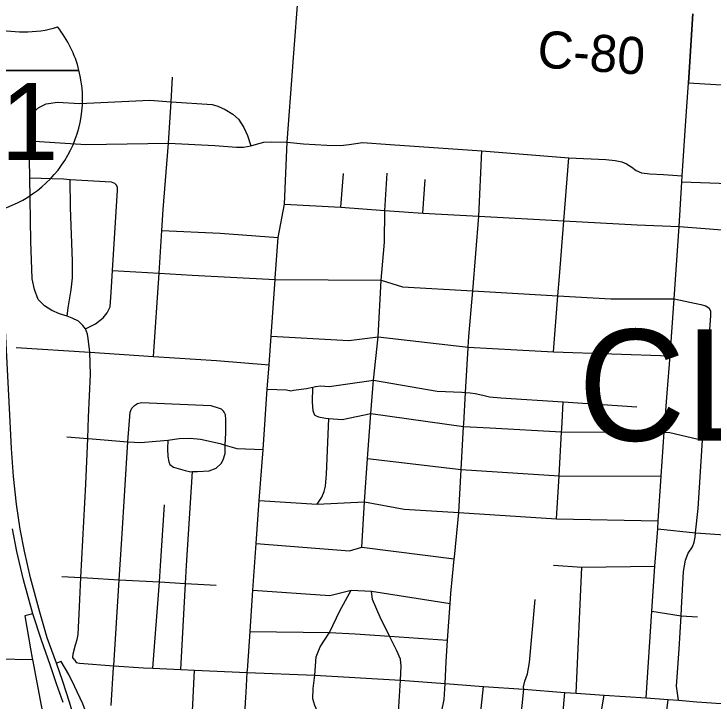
# Model space of a CAD drawing. Extents: x 0 to 34, y 0 to 22.
# Drawn here: x 6.488 to 7.561, y 16.128 to 17.181 of the extents above; entities that cross this region are included whole.
import ezdxf

# ---------------------------------------------------------------- set-up
doc = ezdxf.new("R2010")
doc.units = 0
for name, color, linetype in [('GM_X_City_Street', 7, 'Continuous'), ('GM_X_County_Road', 7, 'Continuous'), ('GM_X_County_Road_Text', 7, 'Continuous'), ('GM_X_Interchange_Ramps', 7, 'Continuous'), ('GM_X_Interstate_Route', 7, 'Continuous'), ('GM_X_Interstate_Shield', 7, 'Continuous'), ('GM_X_Township_Text', 7, 'Continuous')]:
    doc.layers.add(name, color=color, linetype=linetype)

msp = doc.modelspace()

# ---------------------------------------------------------------- linework, layer by layer
at = {"layer": 'GM_X_City_Street'}
for p, q in [((7.5231, 17.0753), (7.5298, 17.1813)), ((7.5185, 17.0096), (7.5231, 17.0753)), ((6.99, 16.8851), (6.9938, 16.9368)), ((7.1155, 16.876), (7.119, 16.9272)), ((6.5694, 16.5328), (6.6015, 16.5303)), ((7.4757, 16.3921), (7.5338, 16.3856)), ((7.3509, 16.14), (7.3593, 16.3332)), ((6.4444, 16.1929), (6.5167, 16.1915)), ((6.8444, 16.141), (6.8462, 16.1716))]:
    msp.add_line(p, q, dxfattribs=at)
for points in [[(6.9167, 17.1078), (6.9254, 17.2217), (6.938, 17.4228), (6.9444, 17.5239), (6.9541, 17.675), (6.9597, 17.764), (6.9633, 17.8201), (6.9689, 17.9079), (6.973, 17.9724), (6.9772, 18.0377), (6.9864, 18.1488)], [(6.8469, 16.1818), (6.8505, 16.2343), (6.8548, 16.298), (6.8597, 16.3693), (6.8646, 16.4353), (6.8705, 16.5136), (6.877, 16.606), (6.8797, 16.6435), (6.8828, 16.6872), (6.8889, 16.7741), (6.8891, 16.7759), (6.8935, 16.8385), (6.9033, 16.8894), (6.9074, 16.9846), (6.9161, 17.1002), (6.9167, 17.1078)], [(6.7027, 16.6561), (6.7111, 16.7836), (6.7154, 16.8492), (6.7175, 16.8815), (6.7257, 16.983), (6.7293, 17.0465), (6.7314, 17.0841)], [(6.525, 17.0367), (6.5295, 17.0394), (6.5379, 17.0435), (6.555, 17.046), (6.5895, 17.0441), (6.6969, 17.0489), (6.7293, 17.0465), (6.7922, 17.0421), (6.801, 17.0397), (6.8123, 17.0349), (6.824, 17.0274), (6.8329, 17.0196), (6.8409, 17.0072), (6.8467, 16.9946), (6.8519, 16.9789)], [(6.5812, 16.1911), (6.5789, 16.1945), (6.579, 16.2002), (6.5829, 16.2142), (6.5853, 16.2222), (6.5868, 16.2298), (6.5888, 16.2723), (6.5911, 16.3172), (6.5985, 16.4605), (6.6015, 16.5303), (6.6028, 16.5629), (6.6057, 16.6286), (6.6047, 16.6625), (6.6025, 16.6837), (6.601, 16.6905), (6.598, 16.6985), (6.5939, 16.7035), (6.5872, 16.71), (6.5777, 16.715), (6.57, 16.7176), (6.5584, 16.7213), (6.5463, 16.7264), (6.5354, 16.7337), (6.5256, 16.7436), (6.5197, 16.7585), (6.5165, 16.7752), (6.5143, 16.8326), (6.5128, 16.9298), (6.5119, 16.9867), (6.5117, 17.0004), (6.5126, 17.0152), (6.5157, 17.0243), (6.5207, 17.0319), (6.525, 17.0367)], [(7.4583, 16.1326), (7.4667, 16.2655), (7.4715, 16.3347), (7.4757, 16.3921), (7.4766, 16.4039), (7.4813, 16.4726), (7.4858, 16.5402), (7.4905, 16.6), (7.495, 16.6573), (7.5009, 16.7446), (7.5088, 16.8554), (7.5126, 16.9236), (7.5132, 16.9329), (7.5185, 17.0096)], [(6.5119, 16.9867), (6.5988, 16.981), (6.7257, 16.983), (6.7963, 16.9797), (6.8298, 16.9769), (6.8407, 16.9768), (6.8519, 16.9789), (6.8604, 16.9814), (6.8715, 16.9844), (6.8832, 16.9853), (6.9074, 16.9846), (6.9327, 16.9821), (6.9684, 16.9802), (6.9894, 16.9795), (7.0023, 16.9808), (7.0127, 16.9827), (7.0228, 16.984), (7.0656, 16.9812), (7.2059, 16.9713), (7.3394, 16.9608), (7.3963, 16.9578), (7.4105, 16.9564), (7.4209, 16.9543), (7.4279, 16.9515), (7.4361, 16.9462), (7.4426, 16.941), (7.451, 16.9375), (7.4636, 16.9359), (7.4845, 16.9348), (7.5132, 16.9329)], [(7.1403, 16.1023), (7.1443, 16.1105), (7.148, 16.1301), (7.1499, 16.1549), (7.1514, 16.1882), (7.1536, 16.2211), (7.1573, 16.2776), (7.1587, 16.2925), (7.1637, 16.346), (7.164, 16.3483), (7.1705, 16.4167), (7.1742, 16.4828), (7.1781, 16.5489), (7.1783, 16.5528), (7.1812, 16.6009), (7.1852, 16.6693), (7.1853, 16.6704), (7.1862, 16.6867), (7.192, 16.7566), (7.2015, 16.8713), (7.2059, 16.9713)], [(7.3157, 16.6632), (7.3227, 16.749), (7.3252, 16.7788), (7.3318, 16.8642), (7.3394, 16.9608)], [(6.5128, 16.9298), (6.5645, 16.9282), (6.5744, 16.9276), (6.6373, 16.924), (6.6426, 16.9217), (6.6452, 16.9194)], [(7.0219, 16.3637), (7.0263, 16.4333), (7.0306, 16.4997), (7.0356, 16.5687), (7.04, 16.6197), (7.0468, 16.6861), (7.0518, 16.7731), (7.0567, 16.8315), (7.0574, 16.8798), (7.0609, 16.9373)], [(6.57, 16.7176), (6.5718, 16.7307), (6.5762, 16.7583), (6.5783, 16.7765), (6.5781, 16.802), (6.5751, 16.8844), (6.5744, 16.9276)], [(6.598, 16.6985), (6.6133, 16.7063), (6.6255, 16.7153), (6.6313, 16.7232), (6.6359, 16.7323), (6.6376, 16.7543), (6.6397, 16.7881), (6.6474, 16.911), (6.6471, 16.9156), (6.6452, 16.9194)], [(7.5126, 16.9236), (7.5701, 16.9219), (7.6237, 16.9188), (7.6813, 16.915), (7.7077, 16.9123)], [(6.9033, 16.8894), (6.99, 16.8851), (7.0574, 16.8798), (7.1155, 16.876), (7.2015, 16.8713), (7.3318, 16.8642), (7.444, 16.858), (7.5088, 16.8554), (7.7004, 16.8406)], [(6.7154, 16.8492), (6.8046, 16.845), (6.8935, 16.8385)], [(6.6397, 16.7881), (6.7111, 16.7836), (6.7619, 16.7805), (6.8889, 16.7741), (7.0518, 16.7731), (7.0845, 16.7629), (7.192, 16.7566), (7.3227, 16.749), (7.4041, 16.7442), (7.5009, 16.7446), (7.5421, 16.7357), (7.5497, 16.7337), (7.5549, 16.7302)], [(7.5078, 16.129), (7.5044, 16.1506), (7.5087, 16.2075), (7.5117, 16.2584), (7.5123, 16.2701), (7.5155, 16.3263), (7.5183, 16.3437), (7.5226, 16.3547), (7.5292, 16.3645), (7.5315, 16.3713), (7.5331, 16.3789), (7.5338, 16.3856), (7.5377, 16.4229), (7.5445, 16.5279), (7.5523, 16.6471), (7.5571, 16.7184), (7.5572, 16.7253), (7.5549, 16.7302)], [(6.8828, 16.6872), (7.0018, 16.6805), (7.0468, 16.6861), (7.1853, 16.6704), (7.2596, 16.6663), (7.3157, 16.6632), (7.495, 16.6573)], [(6.492, 16.6696), (6.6047, 16.6625), (6.7027, 16.6561), (6.799, 16.6499), (6.8797, 16.6435)], [(6.877, 16.606), (6.9063, 16.6048), (6.9131, 16.6036), (6.9173, 16.6043), (6.937, 16.6071), (6.9467, 16.6091), (6.9511, 16.61), (6.9587, 16.6111), (6.972, 16.6102), (7.04, 16.6197), (7.1377, 16.6029), (7.1752, 16.6011), (7.1812, 16.6009), (7.1881, 16.6005), (7.1957, 16.5993), (7.2074, 16.5969), (7.2176, 16.5942), (7.235, 16.5929), (7.3309, 16.5865), (7.4439, 16.5791)], [(6.9511, 16.5656), (6.9499, 16.5656), (6.9473, 16.5725), (6.9463, 16.5862), (6.9467, 16.6091)], [(7.3206, 16.4074), (7.3244, 16.4731), (7.3283, 16.5404), (7.3285, 16.5444), (7.3309, 16.5865)], [(6.6376, 16.1212), (6.6413, 16.1794), (6.6414, 16.182), (6.6498, 16.3139), (6.6537, 16.3758), (6.6632, 16.5253), (6.6668, 16.5706), (6.6692, 16.5766), (6.6731, 16.5807)], [(6.6731, 16.5807), (6.6777, 16.584), (6.6838, 16.5854), (6.7902, 16.5809), (6.8015, 16.5773), (6.8064, 16.5756), (6.8097, 16.5721)], [(6.8124, 16.5201), (6.8132, 16.539), (6.8133, 16.5595), (6.8127, 16.5668), (6.8108, 16.5706), (6.8097, 16.5721)], [(6.9511, 16.5656), (6.9556, 16.5633), (6.9662, 16.5613), (6.9716, 16.5609), (6.992, 16.5592), (7.0356, 16.5687), (7.1781, 16.5489), (7.2183, 16.5467), (7.3283, 16.5404), (7.4858, 16.5402), (7.4945, 16.5396), (7.5445, 16.5279)], [(6.9537, 16.4299), (6.9605, 16.4406), (6.964, 16.4493), (6.9664, 16.4573), (6.9677, 16.4755), (6.9716, 16.5609)], [(6.6015, 16.5303), (6.6084, 16.5297), (6.6632, 16.5253), (6.6825, 16.5243), (6.7064, 16.5261), (6.7243, 16.528), (6.7418, 16.5303), (6.7588, 16.5307), (6.7747, 16.5292), (6.8045, 16.5225), (6.8124, 16.5201), (6.8302, 16.5152), (6.8705, 16.5136)], [(6.7243, 16.528), (6.724, 16.5144), (6.7242, 16.5026), (6.7259, 16.4946), (6.7277, 16.4904), (6.7329, 16.4865), (6.751, 16.4811), (6.7597, 16.4794), (6.7621, 16.4795), (6.7699, 16.4796), (6.7878, 16.4808), (6.7988, 16.4851), (6.8062, 16.4918), (6.8093, 16.4978), (6.8122, 16.5072), (6.8124, 16.5201)], [(7.0306, 16.4997), (7.1742, 16.4828), (7.3244, 16.4731), (7.4813, 16.4726)], [(6.7446, 16.1762), (6.7517, 16.3082), (6.7532, 16.3356), (6.7621, 16.4795)], [(6.7013, 16.1781), (6.7115, 16.3104), (6.7134, 16.3352), (6.7192, 16.4286)], [(6.8646, 16.4353), (6.9537, 16.4299), (7.0263, 16.4333), (7.0867, 16.4219), (7.1705, 16.4167), (7.3206, 16.4074), (7.4766, 16.4039)], [(7.5338, 16.3856), (7.5859, 16.3823), (7.5957, 16.3817), (7.6887, 16.3758), (7.7429, 16.3724), (7.7927, 16.3693), (7.794, 16.3692), (7.7947, 16.3691), (7.8021, 16.3686)], [(6.8597, 16.3693), (7.003, 16.3582), (7.0219, 16.3637), (7.1637, 16.346)], [(7.3157, 16.3362), (7.3593, 16.3332), (7.4715, 16.3347)], [(6.5619, 16.3188), (6.5911, 16.3172), (6.6014, 16.3166), (6.6498, 16.3139), (6.7115, 16.3104), (6.7517, 16.3082), (6.7988, 16.3055)], [(6.8548, 16.298), (6.9728, 16.2894), (7.0056, 16.2977), (7.0367, 16.2962), (7.1573, 16.2776)], [(6.963, 16.1046), (6.9541, 16.1116), (6.9497, 16.1208), (6.9467, 16.1312), (6.9475, 16.1471), (6.9499, 16.1673), (6.9519, 16.1956), (6.9582, 16.2108), (6.9726, 16.233), (6.9882, 16.2659), (7.0056, 16.2977)], [(7.0028, 14.93), (7.0083, 15.046), (7.0115, 15.0984), (7.013, 15.1274), (7.018, 15.2086), (7.0267, 15.3678), (7.0381, 15.5628), (7.0466, 15.7049), (7.0589, 15.85), (7.0692, 15.9713), (7.0729, 16.0317), (7.077, 16.0946), (7.0811, 16.1597), (7.0822, 16.1815), (7.0811, 16.1919), (7.0759, 16.2048), (7.0644, 16.2274), (7.05, 16.2563), (7.0381, 16.2833), (7.0367, 16.2962)], [(7.186, 15.039), (7.1895, 15.1078), (7.1929, 15.1743), (7.1982, 15.2632), (7.2036, 15.352), (7.2068, 15.4104), (7.2196, 15.5508), (7.2262, 15.6871), (7.2263, 15.6891), (7.2401, 15.8332), (7.2424, 15.8578), (7.2566, 16.0106), (7.2706, 16.1462), (7.2698, 16.1495), (7.2721, 16.1585), (7.2763, 16.1698), (7.2792, 16.1871), (7.2876, 16.2833)], [(7.4667, 16.2655), (7.5117, 16.2584), (7.5368, 16.2567)], [(6.8505, 16.2343), (6.9726, 16.233), (7.0119, 16.2308), (7.0644, 16.2274), (7.1536, 16.2211)], [(6.5812, 16.1911), (6.5838, 16.1869), (6.5891, 16.1857), (6.6414, 16.182), (6.6873, 16.1787), (6.7013, 16.1781), (6.7446, 16.1762), (6.7655, 16.1752), (6.8462, 16.1716)], [(6.8462, 16.1716), (6.8463, 16.1735), (6.8464, 16.1745), (6.8469, 16.1818)], [(6.7312, 15.579), (6.7356, 15.6398), (6.7376, 15.6683), (6.7384, 15.6782), (6.7405, 15.7181), (6.7438, 15.7776), (6.7449, 15.7973), (6.7457, 15.8121), (6.7465, 15.8265), (6.7493, 15.8768), (6.7495, 15.8787), (6.7523, 15.9294), (6.7543, 15.9643), (6.7555, 15.987), (6.7587, 16.0471), (6.7621, 16.1122), (6.7655, 16.1752)], [(7.1183, 14.9866), (7.1158, 14.9898), (7.1158, 15), (7.1164, 15.0163), (7.1189, 15.0303), (7.1214, 15.0378), (7.1223, 15.0425), (7.1239, 15.0517), (7.1249, 15.0665), (7.1273, 15.1115), (7.1333, 15.223), (7.1358, 15.2675), (7.1442, 15.4144), (7.1442, 15.4159), (7.1577, 15.555), (7.1638, 15.6726), (7.1656, 15.6911), (7.1722, 15.76), (7.1778, 15.8163), (7.1795, 15.837), (7.1995, 16.0231), (7.196, 16.0294), (7.2087, 16.1503)], [(6.8387, 16.0479), (6.8439, 16.1339), (6.8444, 16.141)], [(7.2801, 14.9329), (7.279, 14.9757), (7.279, 15.036), (7.2786, 15.1026), (7.2778, 15.2648), (7.2782, 15.3396), (7.2767, 15.4062), (7.2778, 15.478), (7.2823, 15.5476), (7.2929, 15.6588), (7.2948, 15.6907), (7.2975, 15.7129), (7.302, 15.7683), (7.3079, 15.8357), (7.3225, 16.0168), (7.3333, 16.1408)], [(7.419, 15.8228), (7.4178, 15.8288), (7.4171, 15.8414), (7.4175, 15.8706), (7.4204, 15.8963), (7.4204, 15.9141), (7.4175, 15.9268), (7.4114, 15.9361), (7.3937, 15.9505), (7.3876, 15.9557), (7.3838, 15.9589), (7.3795, 15.9644), (7.3768, 15.9732), (7.3757, 15.9835), (7.3774, 16.0024), (7.3777, 16.0058), (7.3823, 16.0706), (7.3936, 16.1368)], [(7.4723, 15.5328), (7.4764, 15.593), (7.4677, 15.5947), (7.4606, 15.5973), (7.4562, 15.6016), (7.4534, 15.6096), (7.4523, 15.6233), (7.4535, 15.642), (7.4557, 15.6778), (7.4567, 15.6944), (7.46, 15.7475), (7.4625, 15.7886), (7.4645, 15.8202), (7.4754, 15.9962), (7.4919, 16.13)]]:
    msp.add_lwpolyline(points, dxfattribs=at)
at = {"layer": 'GM_X_County_Road'}
msp.add_line((7.5298, 17.1813), (7.5231, 17.0753), dxfattribs=at)
for points in [[(7.5231, 17.0753), (7.6154, 17.0697), (7.9476, 17.0504), (8.2133, 17.0321), (8.2203, 17.0317), (8.2262, 17.0314)], [(6.8462, 16.1716), (6.9499, 16.1673), (7.0811, 16.1597), (7.1499, 16.1549), (7.2087, 16.1503), (7.2706, 16.1462), (7.3333, 16.1408), (7.3509, 16.14), (7.3936, 16.1368), (7.4583, 16.1326), (7.4919, 16.13), (7.5078, 16.129), (7.536, 16.1269), (7.6025, 16.1222), (7.7152, 16.1151), (7.7857, 16.1102), (7.8462, 16.1057), (7.9125, 16.101), (7.9759, 16.0969), (8.0366, 16.0924), (8.2099, 16.0817), (8.2195, 16.0811)]]:
    msp.add_lwpolyline(points, dxfattribs=at)
at = {"layer": 'GM_X_Interchange_Ramps'}
for points in [[(6.5174, 16.2615), (6.5049, 16.2587), (6.5136, 16.2078), (6.5163, 16.1937)], [(6.5163, 16.1937), (6.5167, 16.1915), (6.5302, 16.1211), (6.5386, 16.0808), (6.5403, 16.0714)], [(6.6127, 16.0642), (6.6111, 16.0729), (6.6034, 16.0983), (6.5939, 16.1237), (6.5814, 16.1505), (6.5725, 16.1684), (6.561, 16.1883), (6.5538, 16.1858)]]:
    msp.add_lwpolyline(points, dxfattribs=at)
at = {"layer": 'GM_X_Interstate_Route'}
for points in [[(6.5538, 16.1858), (6.5395, 16.2249), (6.5281, 16.264), (6.5138, 16.3168), (6.5046, 16.3574), (6.4981, 16.3912), (6.4921, 16.4296), (6.4877, 16.4719), (6.4847, 16.5149), (6.4825, 16.5564), (6.4717, 16.7658), (6.4622, 16.9586), (6.4581, 17.04), (6.4557, 17.0959), (6.4542, 17.128), (6.4522, 17.1639)], [(6.5639, 16.1255), (6.5537, 16.154), (6.5439, 16.1834), (6.5309, 16.2212), (6.5174, 16.2615), (6.5031, 16.3135), (6.493, 16.3569), (6.486, 16.392)], [(6.5782, 15.5976), (6.5864, 15.6422), (6.5976, 15.7038), (6.6068, 15.7565), (6.6099, 15.785), (6.6123, 15.8168), (6.6132, 15.8435), (6.6136, 15.8725), (6.6127, 15.8991), (6.6109, 15.9233), (6.6086, 15.9521), (6.6036, 15.9986), (6.5965, 16.0363), (6.5897, 16.0677), (6.5823, 16.0963), (6.5735, 16.126), (6.5634, 16.1576), (6.5538, 16.1858)]]:
    msp.add_lwpolyline(points, dxfattribs=at)
at = {"layer": 'GM_X_Interstate_Shield'}
for p, q in [((6.3149, 17.0947), (6.5882, 17.0947)), ((6.5882, 17.0947), (6.3149, 17.0947)), ((6.5882, 17.0947), (6.3149, 17.0947))]:
    msp.add_line(p, q, dxfattribs=at)
for centre, start, end in [((6.5034, 17.3311), 253.0091, 286.9909), ((6.416, 17.0512), 14.1934, 38.331), ((6.416, 17.0512), 281.537, 14.1934)]:
    msp.add_arc(centre, 0.1776, start, end, dxfattribs=at)

# ---------------------------------------------------------------- texts
at = {"layer": 'GM_X_County_Road_Text'}
msp.add_text('C-80', height=0.05682, rotation=355.8896, dxfattribs=at).set_placement((7.2899, 17.0995))
at = {"layer": 'GM_X_Interstate_Shield'}
msp.add_text('71', height=0.11837, dxfattribs=at).set_placement((6.3803, 16.9571))
at = {"layer": 'GM_X_Township_Text'}
msp.add_text('CLINTON', height=0.17045, rotation=0, dxfattribs=at).set_placement((7.3537, 16.527))

doc.saveas('drawing.dxf')
